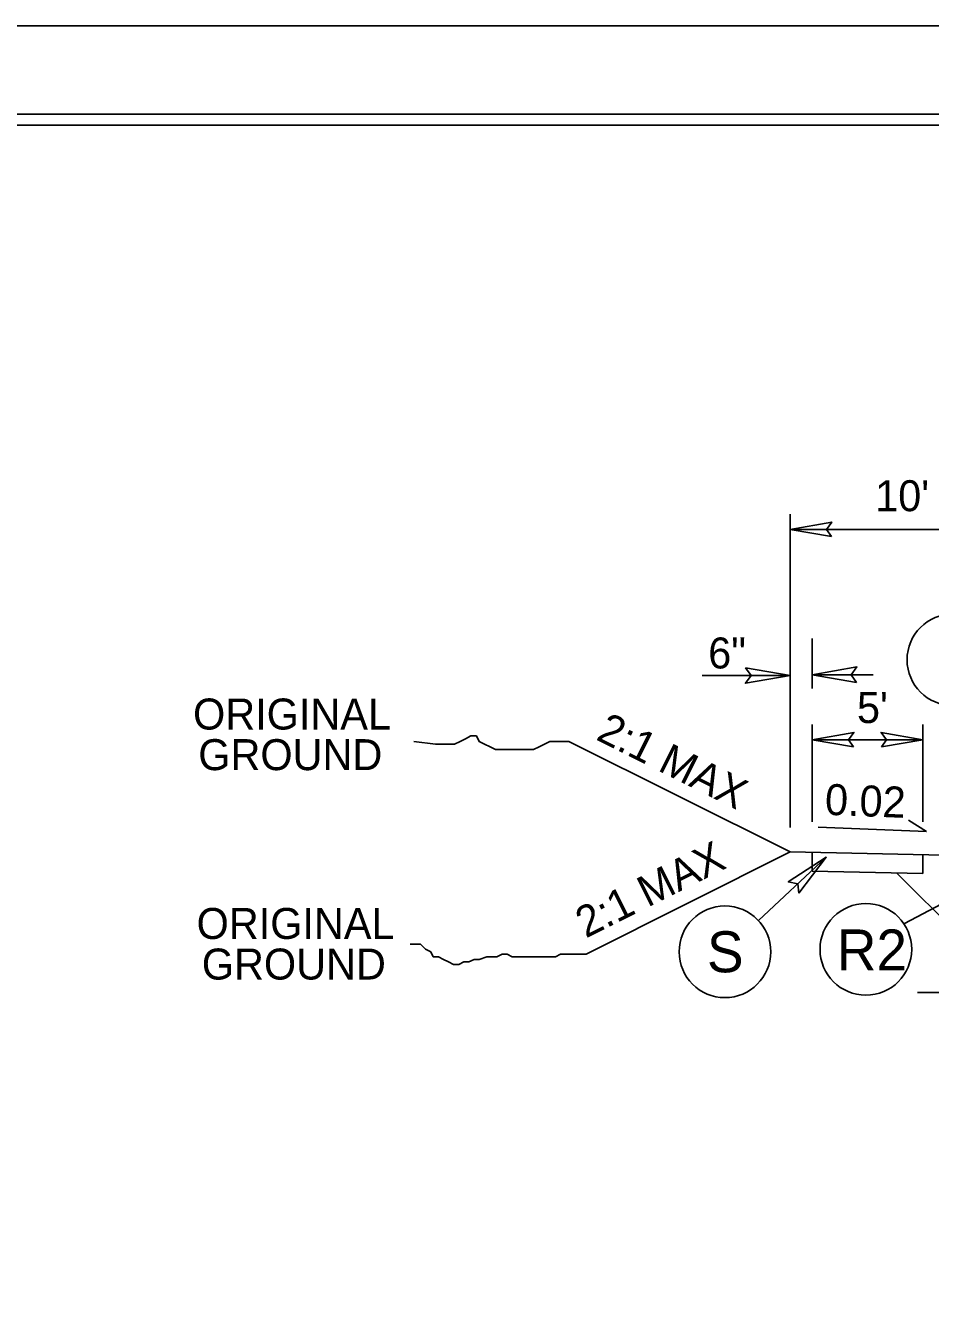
# Model space of a CAD drawing. Extents: x 1640342 to 1730599, y 538663 to 843747.
# Drawn here: x 1729967.5 to 1730008.4, y 539310.4 to 539368.8 of the extents above; entities that cross this region are included whole.
import ezdxf

# ---------------------------------------------------------------- set-up
doc = ezdxf.new("R2010")
doc.units = 0
for name, color, linetype in [('Default', 7, 'Continuous'), ('Sheet Clip Boundary CELL', 7, 'Continuous'), ('Sheet Layout Plan Border', 7, 'Continuous'), ('Sheet Plan CELL', 7, 'Continuous'), ('Sheet Plan Layout CELL', 7, 'Continuous'), ('Sheet Plot Border Inside CELL', 7, 'Continuous'), ('Sheet Plot Border Outside CELL', 7, 'Continuous'), ('Typical Hinge Slope Arterial CELL', 7, 'Continuous'), ('Typical Hinge Slope Interstate CELL', 7, 'Continuous'), ('Typical ID Circle CELL', 7, 'Continuous'), ('Typical Pavement Slope CELL', 7, 'Continuous'), ('Typical Pavement Slope Information CELL', 7, 'Continuous'), ('Typical Shoulder Slope CELL', 7, 'Continuous'), ('Typical Terminator CELL', 7, 'Continuous'), ('Typical Text ID Circle CELL', 7, 'Continuous')]:
    doc.layers.add(name, color=color, linetype=linetype)

msp = doc.modelspace()

# ---------------------------------------------------------------- linework, layer by layer
at = {"layer": 'Default'}
for p, q in [((1730002.066, 539332.548), (1730002.066, 539346.707)), ((1730002.066, 539346.015), (1730012.067, 539346.015)), ((1730003.066, 539341.083), (1730003.066, 539338.823)), ((1729998.097, 539339.419), (1730002.066, 539339.419)), ((1730005.816, 539339.442), (1730003.066, 539339.442)), ((1730003.066, 539332.802), (1730003.066, 539337.204)), ((1730008.066, 539332.802), (1730008.066, 539337.204)), ((1730008.066, 539336.508), (1730003.066, 539336.508)), ((1730007.828, 539325.082), (1730010.558, 539325.082))]:
    msp.add_line(p, q, dxfattribs=at)
for points in [[(1730003.94, 539345.692), (1730002.066, 539346.015), (1730003.951, 539346.348), (1730003.711, 539346.015)], [(1730004.94, 539336.185), (1730003.066, 539336.508), (1730004.95, 539336.841), (1730004.711, 539336.508)], [(1730006.192, 539336.185), (1730008.066, 539336.508), (1730006.181, 539336.841), (1730006.421, 539336.508)]]:
    msp.add_lwpolyline(points, close=True, dxfattribs=at)
at = {"layer": 'Sheet Clip Boundary CELL'}
msp.add_lwpolyline([(1729883.99, 539154.279), (1730163.993, 539154.279), (1730163.993, 539321.981), (1730126.14, 539321.981), (1730126.14, 539364.279), (1729883.99, 539364.279)], close=True, dxfattribs=at)
at = {"layer": 'Sheet Layout Plan Border'}
msp.add_lwpolyline([(1729883.99, 539154.279), (1730163.993, 539154.279), (1730163.993, 539321.981), (1730126.14, 539321.981), (1730126.14, 539364.279), (1729883.99, 539364.279)], close=True, dxfattribs=at)
at = {"layer": 'Sheet Plan CELL'}
for points in [[(1729873.99, 539154.279), (1729873.985, 539364.274), (1730133.983, 539364.281), (1730133.985, 539334.269), (1730173.993, 539334.266), (1730173.993, 539154.279)], [(1730173.998, 539364.279), (1729873.99, 539364.279), (1729873.99, 539154.279), (1730173.993, 539154.279)]]:
    msp.add_lwpolyline(points, close=True, dxfattribs=at)
at = {"layer": 'Sheet Plan Layout CELL'}
msp.add_lwpolyline([(1729873.985, 539364.274), (1729873.99, 539154.279), (1730173.99, 539154.279), (1730173.99, 539321.981), (1730126.14, 539321.981), (1730126.14, 539364.279)], close=True, dxfattribs=at)
at = {"layer": 'Sheet Plot Border Inside CELL'}
msp.add_lwpolyline([(1729843.293, 539153.776), (1730176.49, 539153.779), (1730176.493, 539364.776), (1729843.293, 539364.776)], close=True, dxfattribs=at)
at = {"layer": 'Sheet Plot Border Outside CELL'}
msp.add_lwpolyline([(1729840.693, 539149.776), (1730177.393, 539149.776), (1730177.393, 539368.776), (1729840.693, 539368.776)], close=True, dxfattribs=at)
at = {"layer": 'Typical Hinge Slope Arterial CELL'}
for p, q in [((1729992.073, 539336.431), (1730002.066, 539331.435)), ((1730002.066, 539331.435), (1729992.849, 539326.812))]:
    msp.add_line(p, q, dxfattribs=at)
msp.add_lwpolyline([(1729985.056, 539336.431), (1729986.041, 539336.309), (1729986.287, 539336.309), (1729986.656, 539336.309), (1729986.903, 539336.309), (1729987.149, 539336.431), (1729987.395, 539336.555), (1729987.641, 539336.678), (1729987.887, 539336.678), (1729988.011, 539336.431), (1729988.257, 539336.309), (1729988.503, 539336.185), (1729988.75, 539336.062), (1729988.996, 539336.062), (1729989.242, 539336.062), (1729989.488, 539336.062), (1729989.734, 539336.062), (1729989.98, 539336.062), (1729990.227, 539336.062), (1729990.473, 539336.062), (1729990.719, 539336.185), (1729990.965, 539336.309), (1729991.211, 539336.431), (1729991.581, 539336.431), (1729991.827, 539336.431), (1729992.073, 539336.431)], dxfattribs=at)
at = {"layer": 'Typical Hinge Slope Interstate CELL'}
msp.add_lwpolyline([(1729984.901, 539327.273), (1729985.131, 539327.273), (1729985.361, 539327.273), (1729985.592, 539327.042), (1729985.822, 539326.927), (1729985.938, 539326.696), (1729986.168, 539326.696), (1729986.399, 539326.582), (1729986.629, 539326.466), (1729986.859, 539326.35), (1729987.09, 539326.35), (1729987.32, 539326.466), (1729987.55, 539326.466), (1729987.781, 539326.582), (1729988.011, 539326.582), (1729988.357, 539326.696), (1729988.587, 539326.696), (1729988.818, 539326.696), (1729989.048, 539326.812), (1729989.278, 539326.812), (1729989.509, 539326.696), (1729989.739, 539326.696), (1729989.969, 539326.696), (1729990.2, 539326.696), (1729990.43, 539326.696), (1729990.776, 539326.696), (1729991.121, 539326.696), (1729991.467, 539326.696), (1729991.697, 539326.812), (1729992.042, 539326.812), (1729992.388, 539326.812), (1729992.849, 539326.812)], dxfattribs=at)
at = {"layer": 'Typical ID Circle CELL'}
for p, q in [((1730000.636, 539328.336), (1730003.7, 539331.198)), ((1730007.232, 539328.209), (1730011.707, 539330.552))]:
    msp.add_line(p, q, dxfattribs=at)
for centre in [(1730009.427, 539340.122), (1729999.122, 539326.923), (1730005.493, 539327.034)]:
    msp.add_circle(centre, 2.071, dxfattribs=at)
at = {"layer": 'Typical Pavement Slope CELL'}
msp.add_line((1730006.899, 539330.483), (1730009.622, 539327.76), dxfattribs=at)
at = {"layer": 'Typical Pavement Slope Information CELL'}
for q in [(1730003.332, 539332.558), (1730007.417, 539332.875)]:
    msp.add_line((1730008.231, 539332.361), q, dxfattribs=at)
at = {"layer": 'Typical Shoulder Slope CELL'}
for p, q in [((1730002.066, 539331.435), (1730011.534, 539331.246)), ((1730003.066, 539330.56), (1730003.066, 539331.395)), ((1730008.066, 539331.295), (1730008.066, 539330.46)), ((1730003.066, 539330.56), (1730008.066, 539330.46))]:
    msp.add_line(p, q, dxfattribs=at)
at = {"layer": 'Typical Terminator CELL'}
for points in [[(1730000.058, 539339.764), (1730002.066, 539339.419), (1730000.047, 539339.062), (1730000.304, 539339.419)], [(1730005.074, 539339.097), (1730003.066, 539339.442), (1730005.085, 539339.799), (1730004.828, 539339.442)], [(1730002.469, 539329.575), (1730003.7, 539331.198), (1730001.981, 539330.081), (1730002.412, 539329.995)]]:
    msp.add_lwpolyline(points, close=True, dxfattribs=at)

# ---------------------------------------------------------------- texts
at = {"layer": 'Default'}
for s, p in [("10'", (1730005.913, 539346.837)), ('6"', (1729998.367, 539339.73)), ('ORIGINAL', (1729975.08, 539336.97)), ('GROUND', (1729975.316, 539335.134)), ('ORIGINAL', (1729975.241, 539327.504)), ('GROUND', (1729975.476, 539325.669))]:
    msp.add_text(s, height=1.4, dxfattribs=at).set_placement(p)
msp.add_text("5'", height=1.4, rotation=360, dxfattribs=at).set_placement((1730005.09, 539337.263))
at = {"layer": 'Typical Hinge Slope Interstate CELL'}
for rotation, p in [(333.43542, (1729993.242, 539336.534)), (26.56458, (1729992.833, 539327.523))]:
    msp.add_text('2:1 MAX', height=1.4, rotation=rotation, dxfattribs=at).set_placement(p)
at = {"layer": 'Typical Pavement Slope Information CELL'}
msp.add_text('0.02', height=1.4, rotation=357.69972, dxfattribs=at).set_placement((1730003.622, 539333.12))
at = {"layer": 'Typical Text ID Circle CELL'}
for s, height, p in [('S', 1.854, (1729998.311, 539325.996)), ('R2', 1.8535, (1730004.182, 539326.08))]:
    msp.add_text(s, height=height, dxfattribs=at).set_placement(p)

doc.saveas('drawing.dxf')
